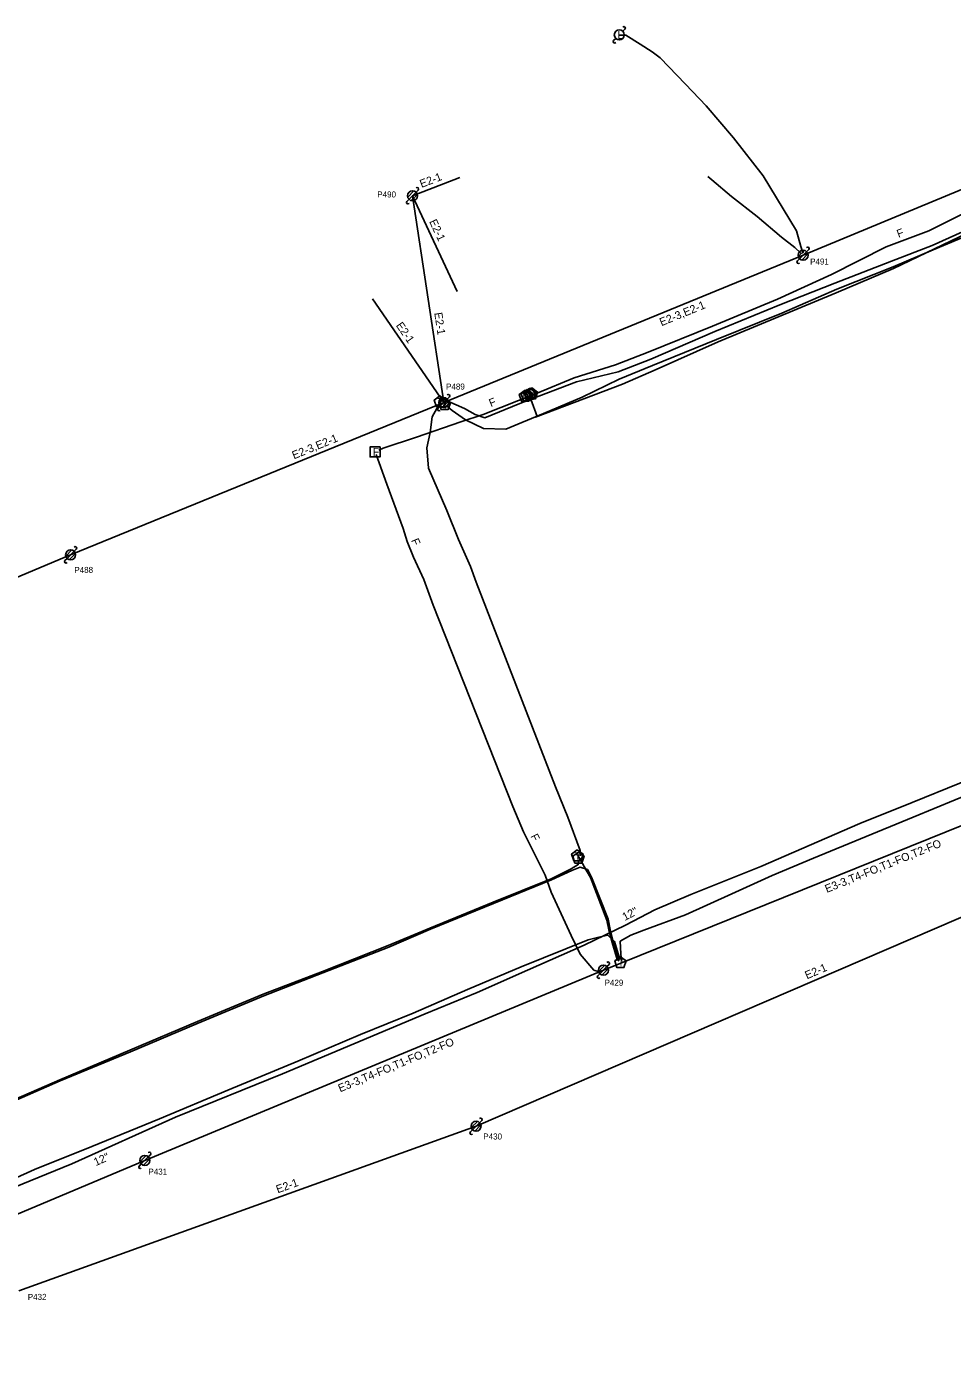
# Model space of a CAD drawing. Extents: x 1741604 to 1825760, y 1164229 to 1194908.
# Drawn here: x 1817305 to 1817768, y 1191605 to 1192271 of the extents above; entities that cross this region are included whole.
import ezdxf

# ---------------------------------------------------------------- set-up
doc = ezdxf.new("R2010")
doc.units = 0
for name, color, linetype in [('RD_EX_SU_Elec', 7, 'Continuous'), ('RD_EX_SU_H2O', 7, 'Continuous'), ('RD_EX_SU_Ovhd', 7, 'Continuous'), ('RD_EX_SU_Pole', 7, 'Continuous'), ('RD_EX_SU_Telecom', 7, 'Continuous'), ('RD_EX_SU_TX_H2O', 7, 'Continuous'), ('RD_EX_SU_TX_Pole', 7, 'Continuous'), ('RD_EX_SU_TX_Telecom', 7, 'Continuous')]:
    doc.layers.add(name, color=color, linetype=linetype)

# ---------------------------------------------------------------- blocks, each defined once
blk = doc.blocks.new('SUE_TPP')
at = {"layer": 'RD_EX_SU_Telecom'}
blk.add_lwpolyline([(0, 3), (-2.85, 0.93), (-1.76, -2.43), (1.76, -2.43), (2.85, 0.93)], close=True, dxfattribs=at)
blk.add_text('T', height=3.75, dxfattribs=at).set_placement((-1.25, -1.88))
blk = doc.blocks.new('SUE_TFOH')
at = {"layer": 'RD_EX_SU_Telecom'}
blk.add_lwpolyline([(2.5, 2.5), (-2.5, 2.5), (-2.5, -2.5), (2.5, -2.5)], close=True, dxfattribs=at)
blk.add_text('F', height=4, dxfattribs=at).set_placement((-1.24, -2))
blk = doc.blocks.new('SUE_PP')
at = {"layer": 'RD_EX_SU_Pole'}
for p, q in [((-2.41, -0.65), (0.65, 2.41)), ((-1.77, -1.77), (1.77, 1.77)), ((-0.65, -2.41), (2.41, 0.65)), ((1.77, 1.77), (2.83, 2.83)), ((-2.83, -2.83), (-1.77, -1.77))]:
    blk.add_line(p, q, dxfattribs=at)
blk.add_circle((0, 0), 2.5, dxfattribs=at)
for centre, start, end in [((2.3, 3.36), 315, 135), ((-2.3, -3.36), 135, 315)]:
    blk.add_arc(centre, 0.75, start, end, dxfattribs=at)
blk = doc.blocks.new('SUE_WM')
at = {"layer": 'RD_EX_SU_H2O'}
blk.add_lwpolyline([(0, 3.05), (-2.9, 0.94), (-1.79, -2.47), (1.79, -2.47), (2.9, 0.94)], close=True, dxfattribs=at)
blk.add_text('M', height=3.75, dxfattribs=at).set_placement((-1.43, -1.88))

msp = doc.modelspace()

# ---------------------------------------------------------------- linework, layer by layer
at = {"layer": 'RD_EX_SU_Elec'}
for points in [[(1817601.32, 1192266.8), (1817604.79, 1192266.84), (1817612.02, 1192262.4), (1817617.98, 1192258.46), (1817621.93, 1192255.49), (1817634.61, 1192242.38), (1817644.86, 1192231.58), (1817658.59, 1192215.57), (1817673.41, 1192196.57), (1817690.07, 1192169.1), (1817692.22, 1192161.2), (1817693.37, 1192157.83)], [(1817645.77, 1192196.22), (1817647.8, 1192194.56), (1817657.56, 1192186.25), (1817670.47, 1192176.15), (1817682.59, 1192165.79), (1817689.17, 1192160.76), (1817692.25, 1192157.93)]]:
    msp.add_lwpolyline(points, dxfattribs=at)
at = {"layer": 'RD_EX_SU_H2O'}
for p, q in [((1817559.63, 1192075.91), (1817603.08, 1192092.32)), ((1817557.27, 1192084.96), (1817560.55, 1192076.26))]:
    msp.add_line(p, q, dxfattribs=at)
for points in [[(1817603.08, 1192092.32), (1817620.02, 1192099.77), (1817650.94, 1192113.53), (1817709.9, 1192137.99), (1817738.54, 1192150.25), (1817779.5, 1192169.8), (1817804.96, 1192180.86), (1817840.04, 1192195.55), (1817919.89, 1192225.52)], [(1817290.58, 1191687.44), (1817327.9, 1191702.6), (1817379.73, 1191725.92), (1817433.3, 1191747.67), (1817504.45, 1191777.59), (1817530.48, 1191788.26), (1817555.69, 1191799.45), (1817583.92, 1191811.86), (1817604.7, 1191821.97), (1817619.34, 1191829.68), (1817637.32, 1191837.29), (1817672.18, 1191851.27), (1817721.7, 1191872.69), (1817747.83, 1191883.31), (1817771.68, 1191892.89), (1817818.2, 1191912.56), (1817840.13, 1191921.49), (1817861.72, 1191929.84), (1817906.97, 1191948.58), (1817990.53, 1191983.2), (1818055.4, 1192010.53), (1818087.53, 1192023.65), (1818122.59, 1192037.5), (1818148.22, 1192047.45)]]:
    msp.add_lwpolyline(points, dxfattribs=at)
at = {"layer": 'RD_EX_SU_Ovhd'}
for p, q in [((1817693.36, 1192156.82), (1817860.95, 1192226.48)), ((1817498.21, 1192186.57), (1817521.85, 1192195.74)), ((1817498.21, 1192186.57), (1817513.76, 1192083.17)), ((1817498.21, 1192186.57), (1817520.53, 1192138.64)), ((1817513.76, 1192083.17), (1817693.36, 1192156.82)), ((1817478.18, 1192135.02), (1817513.76, 1192083.17)), ((1817327.36, 1192007.07), (1817513.76, 1192083.17)), ((1817172.18, 1191942.08), (1817327.36, 1192007.07)), ((1817593.59, 1191799.46), (1817826.41, 1191893.44)), ((1817529.94, 1191721.43), (1817817.11, 1191845.13)), ((1817364.41, 1191704.35), (1817593.59, 1191799.46)), ((1817301.42, 1191639.15), (1817529.94, 1191721.43)), ((1817129.61, 1191605.39), (1817364.41, 1191704.35))]:
    msp.add_line(p, q, dxfattribs=at)
at = {"layer": 'RD_EX_SU_Pole'}
for p, q in [((1817598.69, 1192264.16), (1817599.75, 1192265.23)), ((1817603.28, 1192268.76), (1817604.34, 1192269.82)), ((1817495.39, 1192183.75), (1817496.45, 1192184.81)), ((1817495.8, 1192185.93), (1817498.86, 1192188.99)), ((1817496.45, 1192184.81), (1817499.98, 1192188.34)), ((1817497.57, 1192184.16), (1817500.63, 1192187.22)), ((1817499.98, 1192188.34), (1817501.04, 1192189.4)), ((1817511.35, 1192082.53), (1817514.41, 1192085.59)), ((1817512, 1192081.41), (1817515.53, 1192084.94)), ((1817513.12, 1192080.76), (1817516.18, 1192083.82)), ((1817515.53, 1192084.94), (1817516.59, 1192086)), ((1817510.94, 1192080.35), (1817512, 1192081.41)), ((1817324.53, 1192004.24), (1817325.59, 1192005.3)), ((1817324.95, 1192006.42), (1817328.01, 1192009.48)), ((1817325.59, 1192005.3), (1817329.13, 1192008.84)), ((1817326.71, 1192004.65), (1817329.77, 1192007.71)), ((1817329.13, 1192008.84), (1817330.19, 1192009.9)), ((1817531.71, 1191723.19), (1817532.77, 1191724.25)), ((1817527.11, 1191718.6), (1817528.17, 1191719.66)), ((1817527.53, 1191720.78), (1817530.59, 1191723.84)), ((1817528.17, 1191719.66), (1817531.71, 1191723.19)), ((1817529.29, 1191719.01), (1817532.36, 1191722.07)), ((1817361.99, 1191703.71), (1817365.05, 1191706.77)), ((1817362.64, 1191702.59), (1817366.17, 1191706.12)), ((1817363.76, 1191701.94), (1817366.82, 1191705)), ((1817366.17, 1191706.12), (1817367.23, 1191707.18)), ((1817361.58, 1191701.52), (1817362.64, 1191702.59))]:
    msp.add_line(p, q, dxfattribs=at)
for centre in [(1817601.52, 1192266.99), (1817498.21, 1192186.57), (1817513.76, 1192083.17), (1817327.36, 1192007.07), (1817529.94, 1191721.43), (1817364.41, 1191704.35)]:
    msp.add_circle(centre, 2.5, dxfattribs=at)
for centre, start, end in [((1817603.81, 1192270.35), 315, 135), ((1817599.22, 1192263.63), 135, 315), ((1817500.51, 1192189.93), 315, 135), ((1817495.92, 1192183.22), 135, 315), ((1817516.06, 1192086.53), 315, 135), ((1817511.47, 1192079.82), 135, 315), ((1817329.66, 1192010.43), 315, 135), ((1817325.06, 1192003.71), 135, 315), ((1817532.24, 1191724.78), 315, 135), ((1817527.64, 1191718.07), 135, 315), ((1817366.7, 1191707.71), 315, 135), ((1817362.11, 1191700.99), 135, 315)]:
    msp.add_arc(centre, 0.75, start, end, dxfattribs=at)
at = {"layer": 'RD_EX_SU_Telecom'}
for p, q in [((1817529.99, 1191993.35), (1817569.64, 1191891.05)), ((1817508.47, 1191981.96), (1817548.27, 1191881.26)), ((1817581.95, 1191859.3), (1817582.19, 1191856.62))]:
    msp.add_line(p, q, dxfattribs=at)
for points in [[(1817481.39, 1192059.45), (1817483.53, 1192060.35), (1817500.12, 1192065.8), (1817522.3, 1192073.55), (1817533.55, 1192077.23), (1817551.12, 1192084.17), (1817560.4, 1192087.91), (1817578.98, 1192095.57), (1817599.6, 1192102.06), (1817615.92, 1192108.29), (1817648.15, 1192121.42), (1817680.56, 1192134.87), (1817707.63, 1192147.18), (1817734.89, 1192161.05), (1817756.18, 1192169.04), (1817775.46, 1192178.67)], [(1817514.99, 1192081.7), (1817517.97, 1192079.28), (1817524.62, 1192074.57), (1817533.71, 1192070.2), (1817544.8, 1192069.96), (1817563.57, 1192077.78), (1817582.99, 1192085.83), (1817601.47, 1192094.88), (1817618.12, 1192101.77), (1817650.08, 1192114.64), (1817682.76, 1192127.79), (1817710.18, 1192139.86), (1817738.3, 1192150.96), (1817758.3, 1192159.49), (1817806.48, 1192179.71)], [(1817512.8, 1192084.18), (1817513.94, 1192084.56), (1817515.84, 1192083.86), (1817524.13, 1192080.13), (1817529.54, 1192077.2), (1817534.31, 1192075.55), (1817551.75, 1192082.67), (1817561.27, 1192086.31), (1817580.21, 1192093.5), (1817600.89, 1192098.54), (1817617.23, 1192104.93), (1817649.24, 1192118.72), (1817681.82, 1192132.08), (1817709.22, 1192142.91), (1817737.6, 1192153.82), (1817757.92, 1192161.74), (1817778.21, 1192170.9)], [(1817511.82, 1192082.87), (1817508.08, 1192076), (1817507.02, 1192068.15), (1817505.4, 1192060.55), (1817506.1, 1192050.42), (1817515.29, 1192029.19), (1817521.17, 1192014.71)], [(1817480.1, 1192057.24), (1817485.33, 1192042.33), (1817493.51, 1192020.24), (1817495.45, 1192013.74), (1817498.72, 1192005.92)], [(1817521.17, 1192014.71), (1817527.2, 1192001.24), (1817529.99, 1191993.35)], [(1817498.72, 1192005.92), (1817503.82, 1191994.75), (1817508.47, 1191981.96)], [(1817602.59, 1191803.74), (1817602.36, 1191807.55), (1817601.98, 1191813.89), (1817607.35, 1191816.97), (1817613.78, 1191819.5), (1817634.64, 1191827.05), (1817657.81, 1191837.65), (1817677.89, 1191846.75), (1817698.52, 1191855.49), (1817748.3, 1191875.94), (1817800.86, 1191897.65), (1817849.53, 1191915.84), (1817877.68, 1191925.46), (1817909.51, 1191935.77), (1817938.3, 1191943.74), (1817956.33, 1191949.93), (1817967.3, 1191954.36), (1817985.76, 1191961.8), (1818013.59, 1191970.02), (1818013.59, 1191969.99), (1818047.13, 1191977.75), (1818075.01, 1191982.37), (1818138.7, 1191991.3), (1818189.88, 1191996.77)], [(1817569.64, 1191891.05), (1817575.72, 1191875.88), (1817581.95, 1191859.3)], [(1817548.27, 1191881.26), (1817553.71, 1191868.53), (1817561.95, 1191851.94)], [(1817122.11, 1191661.74), (1817161.26, 1191677.24), (1817197.51, 1191691.87), (1817219.14, 1191700.19), (1817237.66, 1191707.72), (1817274.54, 1191723.27), (1817322.19, 1191744.05), (1817357.23, 1191758.63), (1817391.05, 1191773.01), (1817423.88, 1191786.69), (1817453.42, 1191798.09), (1817486.35, 1191810.94), (1817507.22, 1191819.89), (1817538.72, 1191832.71), (1817567.58, 1191844.55), (1817577.79, 1191849.33), (1817582.03, 1191850.92), (1817585.62, 1191849.72), (1817587.61, 1191846.01), (1817595.91, 1191824.97), (1817596.92, 1191819.72), (1817598.39, 1191813.6), (1817600.27, 1191806.76), (1817601.32, 1191803.97)], [(1817274.24, 1191724.02), (1817321.96, 1191744.69), (1817356.93, 1191759.45), (1817390.74, 1191773.72), (1817423.57, 1191787.47), (1817453.16, 1191798.84), (1817486, 1191811.74), (1817506.85, 1191820.43), (1817538.41, 1191833.44), (1817567.47, 1191845.18), (1817577.44, 1191850.02), (1817581.03, 1191852.19), (1817581.11, 1191853.66)], [(1817561.95, 1191851.94), (1817564.55, 1191846.98), (1817567.48, 1191838.49), (1817577.47, 1191816.82), (1817582.01, 1191807.39), (1817588.82, 1191799.49), (1817590.93, 1191798.84), (1817593.13, 1191799.09)], [(1817600.54, 1191804.34), (1817597.88, 1191813.3), (1817596.24, 1191819.56), (1817595.27, 1191824.36), (1817587.11, 1191845.8), (1817585.02, 1191849.39), (1817582.08, 1191854.63), (1817580.82, 1191856.83)], [(1817224.93, 1191656.56), (1817223.35, 1191658.72), (1817222.68, 1191661.97), (1817224.43, 1191664.26), (1817227.42, 1191665.61), (1817243.03, 1191671.76), (1817268.39, 1191682.63), (1817289.64, 1191690.91), (1817309.31, 1191699.77), (1817338, 1191711.32), (1817371.72, 1191725.09), (1817405.93, 1191739.5), (1817440.91, 1191753.97), (1817472.25, 1191767.35), (1817498.47, 1191777.92), (1817525.62, 1191789.85), (1817552.46, 1191801.03), (1817585.96, 1191814.69), (1817591.35, 1191815.94), (1817595.83, 1191817.01), (1817599.13, 1191813.74), (1817601.12, 1191807.09), (1817601.88, 1191804.77)]]:
    msp.add_lwpolyline(points, dxfattribs=at)
msp.add_lwpolyline([(1817602.09, 1191806.16), (1817599.24, 1191804.09), (1817600.33, 1191800.74), (1817603.85, 1191800.74), (1817604.94, 1191804.09)], close=True, dxfattribs=at)

# ---------------------------------------------------------------- block references
at = {"layer": 'RD_EX_SU_H2O'}
for p in [(1817556.81, 1192087.27), (1817557.81, 1192087.5), (1817554.4, 1192086.32), (1817555.44, 1192086.67)]:
    msp.add_blockref('SUE_WM', p, dxfattribs=at)
at = {"layer": 'RD_EX_SU_Pole'}
for p in [(1817693.36, 1192156.82), (1817593.59, 1191799.46)]:
    msp.add_blockref('SUE_PP', p, dxfattribs=at)
at = {"layer": 'RD_EX_SU_Telecom'}
for name, p in [('SUE_TPP', (1817511.92, 1192083.53)), ('SUE_TPP', (1817514.24, 1192082.06)), ('SUE_TFOH', (1817479.52, 1192058.53)), ('SUE_TPP', (1817580.54, 1191856.53)), ('SUE_TPP', (1817581.09, 1191855.42))]:
    msp.add_blockref(name, p, dxfattribs=at)

# ---------------------------------------------------------------- texts
at = {"layer": 'RD_EX_SU_Ovhd'}
for s, rotation, p in [('E2-1', 21.2002, (1817502.71, 1192190.46)), ('E2-1', 294.96792, (1817506.43, 1192173.67)), ('E2-3,E2-1', 22.29659, (1817622.6, 1192121.32)), ('E2-1', 304.46539, (1817489.73, 1192121.72)), ('E2-1', 278.55229, (1817509.05, 1192127.97)), ('E2-3,E2-1', 22.20956, (1817438.95, 1192054.79)), ('E3-3,T4-FO,T1-FO,T2-FO', 21.98243, (1817705.23, 1191838.05)), ('E2-1', 23.30533, (1817695.3, 1191794.84)), ('E3-3,T4-FO,T1-FO,T2-FO', 22.53723, (1817462.01, 1191738.36)), ('E2-1', 19.80098, (1817430.84, 1191687.87))]:
    msp.add_text(s, height=4, rotation=rotation, dxfattribs=at).set_placement(p)
at = {"layer": 'RD_EX_SU_Pole'}
msp.add_text('L', height=4, dxfattribs=at).set_placement((1817600.65, 1192264.99))
at = {"layer": 'RD_EX_SU_Telecom'}
msp.add_text('T', height=3.75, dxfattribs=at).set_placement((1817600.84, 1191801.29))
at = {"layer": 'RD_EX_SU_TX_H2O'}
for rotation, p in [(27.78225, (1817604.29, 1191824.01)), (24.22183, (1817339.95, 1191701.45))]:
    msp.add_text('12"', height=4, rotation=rotation, dxfattribs=at).set_placement(p)
at = {"layer": 'RD_EX_SU_TX_Pole'}
for s, p in [('P490', (1817480.58, 1192185.72)), ('P491', (1817696.88, 1192152.17)), ('P489', (1817514.96, 1192089.68)), ('P488', (1817329.2, 1191998.03)), ('P429', (1817594.16, 1191791.69)), ('P430', (1817533.56, 1191714.8)), ('P431', (1817366.22, 1191697.25)), ('P432', (1817305.93, 1191634.62))]:
    msp.add_text(s, height=3, dxfattribs=at).set_placement(p)
at = {"layer": 'RD_EX_SU_TX_Telecom'}
for rotation, p in [(20.5605, (1817741.04, 1192165.5)), (21.55526, (1817537.33, 1192080.87)), (292.66846, (1817497.38, 1192014.32)), (296.41379, (1817556.99, 1191866.42))]:
    msp.add_text('F', height=4, rotation=rotation, dxfattribs=at).set_placement(p)

doc.saveas('drawing.dxf')
